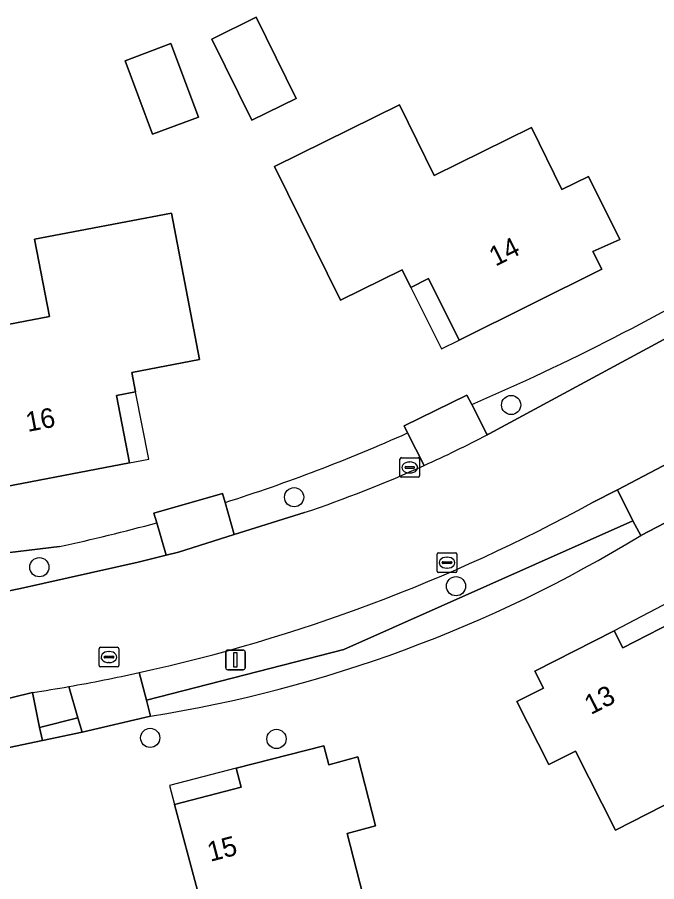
# Model space of a CAD drawing. Extents: x 162661 to 163484, y 380247 to 381230.
# Drawn here: x 163165.49 to 163198.03, y 380935.76 to 380979.76 of the extents above; entities that cross this region are included whole.
import ezdxf

# ---------------------------------------------------------------- set-up
doc = ezdxf.new("R2010")
doc.units = 0
for name, color, linetype in [('IMGEO_Berm_groen', 7, 'Continuous'), ('IMGEO_Boom', 7, 'Continuous'), ('IMGEO_Erf', 7, 'Continuous'), ('IMGEO_Groenvoorziening', 7, 'Continuous'), ('IMGEO_Kolk', 7, 'Continuous'), ('IMGEO_Lichtmast', 7, 'Continuous'), ('IMGEO_Pand', 7, 'Continuous'), ('IMGEO_Pand_nummerreeks', 7, 'Continuous'), ('IMGEO_Pand_overbouw', 7, 'Continuous'), ('IMGEO_Parkeervlak_halfverhard', 7, 'Continuous'), ('IMGEO_Rijbaan_lokaal_gesloten', 7, 'Continuous'), ('IMGEO_Rioolput', 7, 'Continuous'), ('IMGEO_Voetpad_open', 7, 'Continuous')]:
    doc.layers.add(name, color=color, linetype=linetype)

msp = doc.modelspace()

# ---------------------------------------------------------------- linework, layer by layer
at = {"layer": 'IMGEO_Berm_groen'}
for points in [[(163188.618, 380960.055), (163189.407, 380958.507), (163189.459, 380958.535), (163189.512, 380958.562), (163201.978, 380965.301), (163210.08, 380970.25)], [(163186.204, 380956.952), (163185.358, 380958.609)], [(163176.066, 380955.062), (163176.536, 380953.43), (163180.1, 380954.549)], [(163173.076, 380952.383), (163172.59, 380954.032)], [(163167.647, 380952.826), (163163.966, 380952.385), (163162.723, 380952.217)], [(163160.235, 380949.691), (163161.213, 380949.855), (163163.317, 380950.209), (163165.647, 380950.682), (163171.638, 380952.02), (163173.076, 380952.383)]]:
    msp.add_lwpolyline(points, dxfattribs=at)
for centre, radius, start, end in [((163142.661, 381067.299), 116.676, 293.19634, 301.0694), ((163149.182, 381039.434), 88.551, 287.67377, 294.11256), ((163159.187, 381016.624), 65.503, 288.61817, 294.35859), ((163149.386, 381038.403), 87.503, 282.04523, 285.37723)]:
    msp.add_arc(centre, radius, start, end, dxfattribs=at)
at = {"layer": 'IMGEO_Boom'}
for centre in [(163190.625, 380960.026), (163179.579, 380955.333), (163166.611, 380951.769), (163187.82, 380950.801), (163172.255, 380943.082), (163178.684, 380943.029)]:
    msp.add_circle(centre, 0.489, dxfattribs=at)
at = {"layer": 'IMGEO_Erf'}
for points in [[(163179.682, 380975.627), (163177.431, 380974.518), (163175.394, 380978.654), (163177.646, 380979.763)], [(163174.718, 380974.685), (163172.38, 380973.806), (163170.973, 380977.551), (163173.312, 380978.429)], [(163186.716, 380971.712), (163191.659, 380974.147), (163193.214, 380970.989), (163194.569, 380971.656), (163196.156, 380968.451), (163194.789, 380967.835), (163195.236, 380966.94), (163187.975, 380963.325), (163186.418, 380966.458), (163185.525, 380966.014), (163185.081, 380966.909), (163181.941, 380965.362), (163178.588, 380972.168), (163184.949, 380975.301)], [(163174.768, 380962.336), (163171.327, 380961.682), (163171.514, 380960.701), (163170.532, 380960.513), (163171.197, 380957.079), (163163.236, 380955.553), (163163.053, 380956.51), (163161.555, 380956.214), (163160.852, 380959.773), (163162.366, 380960.055), (163161.71, 380963.504), (163167.125, 380964.531), (163166.372, 380968.467), (163173.332, 380969.79)], [(163201.769, 380936.873), (163199.961, 380940.43), (163195.941, 380938.385), (163193.897, 380942.405), (163192.551, 380941.721), (163190.919, 380944.929), (163192.265, 380945.614), (163191.83, 380946.47), (163195.872, 380948.528), (163196.308, 380947.669), (163199.488, 380949.289), (163201.527, 380945.276), (163204.647, 380946.861), (163208.09, 380940.085)], [(163183.407, 380933.857), (163179.031, 380932.725), (163180.033, 380928.853), (163178.271, 380928.397), (163173.169, 380927.077), (163173.006, 380927.706), (163171.265, 380934.435), (163174.663, 380935.314), (163173.498, 380939.683), (163176.877, 380940.574), (163176.631, 380941.544), (163181.092, 380942.677), (163181.341, 380941.708), (163182.821, 380942.11), (163183.729, 380938.599), (163182.277, 380938.223)]]:
    msp.add_lwpolyline(points, close=True, dxfattribs=at)
for points in [[(163185.358, 380958.609), (163185.179, 380958.961), (163188.375, 380960.53), (163188.618, 380960.055)], [(163172.59, 380954.032), (163172.444, 380954.528), (163175.932, 380955.527), (163176.066, 380955.062)], [(163200.525, 380955.104), (163197.229, 380953.39)], [(163162.723, 380952.217), (163163.966, 380952.385), (163167.647, 380952.826)], [(163172.271, 380944.184), (163168.797, 380943.373), (163166.766, 380942.942), (163163.122, 380942.181), (163154.821, 380940.555)]]:
    msp.add_lwpolyline(points, dxfattribs=at)
for centre, radius, start, end in [((163142.661, 381067.299), 116.676, 293.19634, 301.0694), ((163149.182, 381039.434), 88.551, 287.67377, 294.11256), ((163149.386, 381038.403), 87.503, 282.04523, 285.37723), ((163161.416, 381012.046), 68.724, 279.08755, 301.40642)]:
    msp.add_arc(centre, radius, start, end, dxfattribs=at)
at = {"layer": 'IMGEO_Groenvoorziening'}
msp.add_lwpolyline([(163197.229, 380953.39), (163196.821, 380954.138), (163182.117, 380947.576), (163172.059, 380944.999), (163172.271, 380944.184)], dxfattribs=at)
msp.add_lwpolyline([(163168.579, 380944.108), (163166.62, 380943.606), (163166.766, 380942.942), (163168.797, 380943.373)], close=True, dxfattribs=at)
msp.add_arc((163161.416, 381012.046), 68.724, 279.08755, 301.40642, dxfattribs=at)
at = {"layer": 'IMGEO_Kolk'}
for p, q in [((163184.964, 380956.42), (163184.964, 380957.272)), ((163185.039, 380957.346), (163185.891, 380957.346)), ((163185.965, 380957.272), (163185.965, 380956.42)), ((163185.223, 380956.84), (163185.223, 380956.852)), ((163185.661, 380956.803), (163185.263, 380956.803)), ((163185.266, 380956.889), (163185.664, 380956.889)), ((163185.452, 380957.126), (163185.477, 380957.126)), ((163185.707, 380956.852), (163185.707, 380956.84)), ((163185.891, 380956.346), (163185.039, 380956.346)), ((163185.475, 380956.566), (163185.45, 380956.566)), ((163186.86, 380951.576), (163186.86, 380952.428)), ((163186.935, 380952.502), (163187.787, 380952.502)), ((163187.861, 380952.428), (163187.861, 380951.576)), ((163187.119, 380951.996), (163187.119, 380952.008)), ((163187.557, 380951.959), (163187.159, 380951.959)), ((163187.162, 380952.045), (163187.56, 380952.045)), ((163187.348, 380952.282), (163187.373, 380952.282)), ((163187.603, 380952.008), (163187.603, 380951.996)), ((163187.787, 380951.502), (163186.935, 380951.502)), ((163187.371, 380951.722), (163187.346, 380951.722))]:
    msp.add_line(p, q, dxfattribs=at)
for points in [[(163184.964, 380956.42), (163184.964, 380957.272)], [(163185.039, 380957.346), (163185.891, 380957.346)], [(163185.965, 380957.272), (163185.965, 380956.42)], [(163185.891, 380956.346), (163185.039, 380956.346)], [(163186.86, 380951.576), (163186.86, 380952.428)], [(163186.935, 380952.502), (163187.787, 380952.502)], [(163187.861, 380952.428), (163187.861, 380951.576)], [(163187.787, 380951.502), (163186.935, 380951.502)]]:
    msp.add_lwpolyline(points, dxfattribs=at)
for centre, radius, start, end in [((163185.041, 380957.27), 0.0765, 91.552, 178.448), ((163185.041, 380957.27), 0.0765, 91.552, 178.448), ((163185.889, 380957.27), 0.0765, 1.552, 88.448), ((163185.889, 380957.27), 0.0765, 1.552, 88.448), ((163185.263, 380956.849), 0.0403, 85.8775, 175.7526), ((163185.26, 380956.839), 0.0366, 178.938, 274.7102), ((163185.664, 380956.846), 0.043, 264.8664, 352.4533), ((163185.668, 380956.851), 0.0386, 1.7309, 96.639), ((163185.041, 380956.422), 0.0765, 181.552, 268.448), ((163185.041, 380956.422), 0.0765, 181.552, 268.448), ((163185.889, 380956.422), 0.0765, 271.552, 358.448), ((163185.889, 380956.422), 0.0765, 271.552, 358.448), ((163186.937, 380952.426), 0.0765, 91.552, 178.448), ((163186.937, 380952.426), 0.0765, 91.552, 178.448), ((163187.785, 380952.426), 0.0765, 1.552, 88.448), ((163187.785, 380952.426), 0.0765, 1.552, 88.448), ((163187.159, 380952.005), 0.0403, 85.8775, 175.7526), ((163187.156, 380951.995), 0.0366, 178.938, 274.7102), ((163187.56, 380952.002), 0.043, 264.8664, 352.4533), ((163187.564, 380952.007), 0.0386, 1.7309, 96.639), ((163186.937, 380951.578), 0.0765, 181.552, 268.448), ((163186.937, 380951.578), 0.0765, 181.552, 268.448), ((163187.785, 380951.578), 0.0765, 271.552, 358.448), ((163187.785, 380951.578), 0.0765, 271.552, 358.448)]:
    msp.add_arc(centre, radius, start, end, dxfattribs=at)
for centre, major_axis, ratio, start_param, end_param in [((163185.451, 380956.846), (-0.387, 0.002), 0.722429, 4.712389, 7.853982), ((163185.476, 380956.846), (-0.39, 0.002), 0.717154, 1.570796, 4.712389), ((163187.347, 380952.002), (-0.387, 0.002), 0.722429, 4.712389, 7.853982), ((163187.372, 380952.002), (-0.39, 0.002), 0.717154, 1.570796, 4.712389)]:
    msp.add_ellipse(centre, major_axis=major_axis, ratio=ratio, start_param=start_param, end_param=end_param, dxfattribs=at)
at = {"layer": 'IMGEO_Lichtmast'}
for p, q in [((163176.198, 380947.55), (163176.988, 380947.55)), ((163176.988, 380947.55), (163176.198, 380947.55)), ((163176.098, 380946.65), (163176.098, 380947.45)), ((163176.098, 380947.45), (163176.098, 380946.65)), ((163177.088, 380947.45), (163177.088, 380946.65)), ((163177.088, 380946.65), (163177.088, 380947.45)), ((163176.988, 380946.55), (163176.198, 380946.55)), ((163176.198, 380946.55), (163176.988, 380946.55))]:
    msp.add_line(p, q, dxfattribs=at)
msp.add_lwpolyline([(163176.518, 380947.425), (163176.668, 380947.425), (163176.668, 380946.675), (163176.518, 380946.675), (163176.518, 380947.425)], dxfattribs=at)
for centre, start, end in [((163176.198, 380947.45), 90, 180), ((163176.198, 380947.45), 90, 180), ((163176.988, 380947.45), 0, 90), ((163176.988, 380947.45), 360, 90), ((163176.198, 380946.65), 180, 270), ((163176.198, 380946.65), 180, 270), ((163176.988, 380946.65), 270, 0), ((163176.988, 380946.65), 270, 0)]:
    msp.add_arc(centre, 0.1, start, end, dxfattribs=at)
at = {"layer": 'IMGEO_Pand'}
for points in [[(163177.431, 380974.518), (163179.682, 380975.627), (163177.646, 380979.763), (163175.394, 380978.654)], [(163172.38, 380973.806), (163174.718, 380974.685), (163173.312, 380978.429), (163170.973, 380977.551)], [(163185.525, 380966.014), (163186.418, 380966.458), (163187.975, 380963.325), (163195.236, 380966.94), (163194.789, 380967.835), (163196.156, 380968.451), (163194.569, 380971.656), (163193.214, 380970.989), (163191.659, 380974.147), (163186.716, 380971.712), (163184.949, 380975.301), (163178.588, 380972.168), (163181.941, 380965.362), (163185.081, 380966.909)], [(163171.514, 380960.701), (163171.327, 380961.682), (163174.768, 380962.336), (163173.332, 380969.79), (163166.372, 380968.467), (163167.125, 380964.531), (163161.71, 380963.504), (163162.366, 380960.055), (163160.852, 380959.773), (163161.555, 380956.214), (163163.053, 380956.51), (163163.236, 380955.553), (163171.197, 380957.079), (163170.532, 380960.513)], [(163195.872, 380948.528), (163191.83, 380946.47), (163192.265, 380945.614), (163190.919, 380944.929), (163192.551, 380941.721), (163193.897, 380942.405), (163195.941, 380938.385), (163199.961, 380940.43), (163201.769, 380936.873), (163208.09, 380940.085), (163204.647, 380946.861), (163201.527, 380945.276), (163199.488, 380949.289), (163196.308, 380947.669)], [(163173.498, 380939.683), (163174.663, 380935.314), (163171.265, 380934.435), (163173.006, 380927.706), (163173.169, 380927.077), (163178.271, 380928.397), (163180.033, 380928.853), (163179.031, 380932.725), (163183.407, 380933.857), (163182.277, 380938.223), (163183.729, 380938.599), (163182.821, 380942.11), (163181.341, 380941.708), (163181.092, 380942.677), (163176.631, 380941.544), (163176.877, 380940.574)]]:
    msp.add_lwpolyline(points, close=True, dxfattribs=at)
at = {"layer": 'IMGEO_Pand_overbouw'}
for points in [[(163187.975, 380963.325), (163186.418, 380966.458), (163185.525, 380966.014), (163187.079, 380962.88)], [(163171.514, 380960.701), (163170.532, 380960.513), (163171.197, 380957.079), (163172.179, 380957.268)], [(163195.872, 380948.528), (163196.308, 380947.669), (163199.488, 380949.289), (163199, 380950.173)], [(163173.498, 380939.683), (163176.877, 380940.574), (163176.631, 380941.544), (163173.245, 380940.651)]]:
    msp.add_lwpolyline(points, close=True, dxfattribs=at)
at = {"layer": 'IMGEO_Parkeervlak_halfverhard'}
for points in [[(163196.821, 380954.138), (163196.046, 380955.709), (163194.732, 380955.043)], [(163171.693, 380946.405), (163172.059, 380944.999), (163182.117, 380947.576), (163196.821, 380954.138)], [(163166.271, 380945.391), (163166.62, 380943.606), (163168.579, 380944.108), (163168.108, 380945.695)]]:
    msp.add_lwpolyline(points, dxfattribs=at)
for centre, radius, start, end in [((163153.03, 381031.226), 86.85, 282.409, 298.696), ((163153.08, 381030.804), 86.426, 278.77935, 280.01377)]:
    msp.add_arc(centre, radius, start, end, dxfattribs=at)
at = {"layer": 'IMGEO_Rijbaan_lokaal_gesloten'}
for points in [[(163210.08, 380970.25), (163201.978, 380965.301), (163189.512, 380958.562), (163189.459, 380958.535), (163189.407, 380958.507)], [(163194.732, 380955.043), (163196.046, 380955.709), (163199.324, 380957.433), (163200.342, 380958.007), (163205.303, 380960.801), (163206.407, 380961.386)], [(163180.1, 380954.549), (163176.536, 380953.43), (163173.692, 380952.538), (163173.076, 380952.383), (163171.638, 380952.02), (163165.647, 380950.682), (163163.317, 380950.209), (163161.213, 380949.855), (163162.268, 380944.505), (163162.608, 380944.567), (163164.253, 380944.893), (163166.271, 380945.391)]]:
    msp.add_lwpolyline(points, dxfattribs=at)
for centre, radius, start, end in [((163158.886, 381017.298), 66.241, 294.35572, 297.43579), ((163159.187, 381016.624), 65.503, 288.61817, 294.35859), ((163153.03, 381031.226), 86.85, 282.409, 298.696), ((163153.112, 381030.818), 86.434, 279.99093, 282.41371), ((163153.08, 381030.804), 86.426, 278.77935, 280.01377)]:
    msp.add_arc(centre, radius, start, end, dxfattribs=at)
at = {"layer": 'IMGEO_Rioolput'}
for p, q in [((163169.655, 380946.77), (163169.655, 380947.622)), ((163169.73, 380947.696), (163170.582, 380947.696)), ((163170.656, 380947.622), (163170.656, 380946.77)), ((163169.914, 380947.19), (163169.914, 380947.202)), ((163170.352, 380947.153), (163169.954, 380947.153)), ((163169.957, 380947.239), (163170.355, 380947.239)), ((163170.143, 380947.476), (163170.168, 380947.476)), ((163170.398, 380947.202), (163170.398, 380947.19)), ((163170.582, 380946.696), (163169.73, 380946.696)), ((163170.166, 380946.916), (163170.141, 380946.916))]:
    msp.add_line(p, q, dxfattribs=at)
for points in [[(163169.655, 380946.77), (163169.655, 380947.622)], [(163169.73, 380947.696), (163170.582, 380947.696)], [(163170.656, 380947.622), (163170.656, 380946.77)], [(163170.582, 380946.696), (163169.73, 380946.696)]]:
    msp.add_lwpolyline(points, dxfattribs=at)
for centre, radius, start, end in [((163169.732, 380947.62), 0.0765, 91.552, 178.448), ((163169.732, 380947.62), 0.0765, 91.552, 178.448), ((163170.58, 380947.62), 0.0765, 1.552, 88.448), ((163170.58, 380947.62), 0.0765, 1.552, 88.448), ((163169.954, 380947.199), 0.0403, 85.8775, 175.7526), ((163169.951, 380947.189), 0.0366, 178.938, 274.7102), ((163170.355, 380947.196), 0.043, 264.8664, 352.4533), ((163170.359, 380947.201), 0.0386, 1.7309, 96.639), ((163169.732, 380946.772), 0.0765, 181.552, 268.448), ((163169.732, 380946.772), 0.0765, 181.552, 268.448), ((163170.58, 380946.772), 0.0765, 271.552, 358.448), ((163170.58, 380946.772), 0.0765, 271.552, 358.448)]:
    msp.add_arc(centre, radius, start, end, dxfattribs=at)
for centre, major_axis, ratio, start_param, end_param in [((163170.142, 380947.196), (-0.387, 0.002), 0.722429, 4.712389, 7.853982), ((163170.167, 380947.196), (-0.39, 0.002), 0.717154, 1.570796, 4.712389)]:
    msp.add_ellipse(centre, major_axis=major_axis, ratio=ratio, start_param=start_param, end_param=end_param, dxfattribs=at)
at = {"layer": 'IMGEO_Voetpad_open'}
for points in [[(163189.407, 380958.507), (163188.618, 380960.055), (163188.375, 380960.53), (163185.179, 380958.961), (163185.358, 380958.609), (163186.204, 380956.952)], [(163168.108, 380945.695), (163168.579, 380944.108), (163168.797, 380943.373), (163172.271, 380944.184), (163172.059, 380944.999), (163171.693, 380946.405)]]:
    msp.add_lwpolyline(points, dxfattribs=at)
for points in [[(163197.229, 380953.39), (163200.525, 380955.104), (163200.108, 380955.914), (163199.324, 380957.433), (163196.046, 380955.709), (163196.821, 380954.138)], [(163173.076, 380952.383), (163173.692, 380952.538), (163176.536, 380953.43), (163176.066, 380955.062), (163175.932, 380955.527), (163172.444, 380954.528), (163172.59, 380954.032)], [(163164.253, 380944.893), (163162.608, 380944.567), (163162.969, 380942.879), (163163.122, 380942.181), (163166.766, 380942.942), (163166.62, 380943.606), (163166.271, 380945.391)]]:
    msp.add_lwpolyline(points, close=True, dxfattribs=at)
for centre, radius, start, end in [((163158.886, 381017.298), 66.241, 294.35572, 297.43579), ((163153.112, 381030.818), 86.434, 279.99093, 282.41371)]:
    msp.add_arc(centre, radius, start, end, dxfattribs=at)

# ---------------------------------------------------------------- texts
at = {"layer": 'IMGEO_Pand_nummerreeks'}
for s, rotation, p in [('14', 26.4677, (163189.827, 380967.062)), ('16', 10.8498, (163166.023, 380958.653)), ('13', 26.9806, (163194.684, 380944.243)), ('15', 14.7706, (163175.316, 380936.771))]:
    msp.add_text(s, height=1, rotation=rotation, dxfattribs=at).set_placement(p)

doc.saveas('drawing.dxf')
